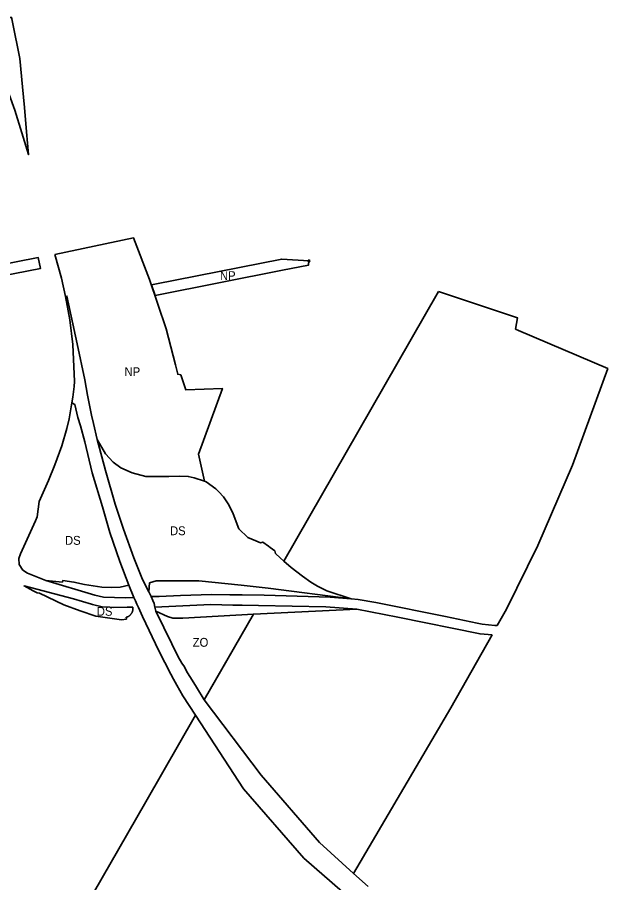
# Model space of a CAD drawing. Extents: x -650276 to -642489, y -1074311 to -1066658.
# Drawn here: x -647860 to -647061, y -1068126 to -1066956 of the extents above; entities that cross this region are included whole.
import ezdxf

# ---------------------------------------------------------------- set-up
doc = ezdxf.new("R2010")
doc.units = 0
doc.header["$LTSCALE"] = 4.8
doc.header["$PDMODE"] = 32
doc.header["$PDSIZE"] = 2.4
for name, color, linetype, lineweight in [('24', 7, 'Continuous', 35), ('25', 7, 'Continuous', 35), ('42', 7, 'Continuous', 35), ('48', 7, 'Continuous', 35)]:
    doc.layers.add(name, color=color, linetype=linetype, lineweight=lineweight)
doc.layers.add('62', color=7, linetype='Continuous')

msp = doc.modelspace()

# ---------------------------------------------------------------- linework, layer by layer
at = {"layer": '24'}
for points in [[(-647876.57, -1067043.5), (-647863.04, -1067081.36), (-647853.65, -1067111.91), (-647844.3, -1067141.25), (-647847.09, -1067110.58), (-647850.07, -1067077.71), (-647852.63, -1067049.52), (-647856.11, -1067011.21), (-647866.14, -1066961.98), (-647867.46, -1066955.52), (-647905.28, -1066967.07), (-647903.5, -1066972.05)], [(-647754.88, -1067737.59), (-647743.12, -1067739.93), (-647728.29, -1067740.64), (-647713.15, -1067741), (-647702.21, -1067740.43), (-647708.71, -1067723.99), (-647720.45, -1067726.49), (-647732.71, -1067727.02), (-647745.41, -1067726.6), (-647768.53, -1067722.82), (-647783.13, -1067719.68), (-647798.17, -1067717.58), (-647798.5, -1067719.67), (-647821.02, -1067717.33)], [(-647596.91, -1067736.61), (-647572.33, -1067737.03), (-647555.58, -1067736.71), (-647525.685, -1067737.542), (-647436.72, -1067740.02), (-647408.2, -1067742.37), (-647520.145, -1067727.879), (-647557, -1067724), (-647614, -1067718), (-647643, -1067718), (-647672, -1067718), (-647680.804, -1067720.745), (-647681.91, -1067732.74), (-647678.66, -1067739.38), (-647678.66, -1067739.38), (-647667.76, -1067739.01), (-647638.75, -1067738.03)], [(-647540.208, -1067762.876), (-647400.63, -1067756.19), (-647442.6, -1067753.13), (-647533.597, -1067751.344), (-647555.67, -1067750.91), (-647568.36, -1067750.7), (-647597.83, -1067750.21), (-647673.47, -1067753.48), (-647672.05, -1067758.98), (-647672.05, -1067758.98), (-647656.469, -1067766.309), (-647649.22, -1067768.38), (-647635.758, -1067768.38)], [(-647540.208, -1067762.876), (-647400.63, -1067756.19), (-647442.6, -1067753.13), (-647533.597, -1067751.344), (-647555.67, -1067750.91), (-647568.36, -1067750.7), (-647597.83, -1067750.21), (-647673.47, -1067753.48), (-647672.05, -1067758.98), (-647672.05, -1067758.98), (-647656.469, -1067766.309), (-647649.22, -1067768.38), (-647635.758, -1067768.38)]]:
    msp.add_lwpolyline(points, close=True, dxfattribs=at)
for points in [[(-647606.818, -1067879.061), (-647617.25, -1067861.95), (-647625.37, -1067848.86), (-647630.3, -1067841.02), (-647633.69, -1067834.31), (-647637.21, -1067829.29), (-647642.29, -1067820.76), (-647650.8, -1067803.28), (-647672.05, -1067758.98), (-647673.47, -1067753.48), (-647673.47, -1067753.48), (-647674.67, -1067748.73), (-647676.47, -1067744.5), (-647678.66, -1067739.38), (-647681.91, -1067732.74), (-647690.09, -1067716.05), (-647702.04, -1067686.86), (-647715.92, -1067648.12), (-647727.37, -1067614.33), (-647740.49, -1067568.67), (-647751.41, -1067526.58), (-647756.55, -1067505.32), (-647759.16, -1067494.01), (-647764.89, -1067466.64), (-647768.5, -1067446.04), (-647778.78, -1067397.1), (-647792.52, -1067332.74), (-647794.54, -1067333.14), (-647788.77, -1067365.03), (-647784.55, -1067398.01), (-647782.39, -1067448.34), (-647782.5, -1067455.11), (-647784.36, -1067469.6), (-647785.64, -1067477.02), (-647781.85, -1067479.19), (-647777.55, -1067496.95), (-647773.96, -1067508.48), (-647768.5, -1067529.75), (-647758.25, -1067571.79), (-647744.61, -1067617.96), (-647734.63, -1067652.57), (-647721.05, -1067691.73), (-647708.71, -1067723.99), (-647702.21, -1067740.43), (-647699.89, -1067745.24), (-647697.85, -1067749.46), (-647695.71, -1067753.9), (-647690.19, -1067766.37), (-647668.13, -1067812.76), (-647651.94, -1067844.36), (-647648.33, -1067851.17), (-647643.83, -1067859.13), (-647635.77, -1067873.43), (-647618.773, -1067899.914)], [(-647708.71, -1067723.99), (-647721.05, -1067691.73), (-647734.63, -1067652.57), (-647744.61, -1067617.96), (-647758.25, -1067571.79), (-647768.5, -1067529.75), (-647773.96, -1067508.48), (-647777.55, -1067496.95), (-647781.85, -1067479.19), (-647785.64, -1067477.02), (-647789.39, -1067498.84), (-647792.54, -1067511.85), (-647799.39, -1067535.48)], [(-647654.743, -1067576.996), (-647685.968, -1067576.68), (-647704.458, -1067572.034), (-647719.661, -1067564.884), (-647729.802, -1067557.462), (-647740.124, -1067546.265), (-647751.41, -1067526.58)], [(-647751.41, -1067526.58), (-647740.49, -1067568.67), (-647727.37, -1067614.33), (-647715.92, -1067648.12), (-647702.04, -1067686.86)], [(-647799.39, -1067535.48), (-647808.71, -1067561.03), (-647817.59, -1067582.4)], [(-647817.59, -1067582.4), (-647829.97, -1067610.62), (-647832.8, -1067631.53), (-647835.06, -1067637.01), (-647855.24, -1067681.26), (-647857.51, -1067687.74), (-647856.9, -1067695.97)], [(-647606.559, -1067583.309), (-647620.586, -1067578.478), (-647628.441, -1067576.759), (-647640.087, -1067576.306), (-647654.743, -1067576.996)], [(-647547.663, -1067659.519), (-647560.187, -1067647.458), (-647567.744, -1067627.24), (-647573.605, -1067614.951), (-647580.539, -1067604.432), (-647586.864, -1067597.411), (-647591.227, -1067593.613), (-647604.415, -1067584.047), (-647606.559, -1067583.309)], [(-647499.095, -1067691.163), (-647503.97, -1067686.73), (-647510.6, -1067680.86), (-647511.24, -1067677.53), (-647517.74, -1067672.85), (-647520.13, -1067671.13), (-647527.76, -1067665.65), (-647530.82, -1067666.65), (-647536.83, -1067663.64), (-647547.663, -1067659.519)], [(-647702.04, -1067686.86), (-647690.09, -1067716.05), (-647681.91, -1067732.74)], [(-647856.9, -1067695.97), (-647852.3, -1067703.36), (-647845.74, -1067707.59), (-647821.02, -1067717.33)], [(-647462.45, -1067719.84), (-647474.13, -1067711.81), (-647489.3, -1067700.07), (-647499.095, -1067691.163)], [(-647783.54, -1067742.11), (-647850.45, -1067724.77), (-647838.18, -1067731.62), (-647832.56, -1067734.22), (-647829.49, -1067734.58), (-647796.87, -1067750.25), (-647774.54, -1067758.68), (-647753.53, -1067765.58), (-647718.54, -1067770.6), (-647712.01, -1067769.63), (-647712.26, -1067767.28)], [(-647821.02, -1067717.33), (-647798.5, -1067719.67), (-647798.17, -1067717.58), (-647783.13, -1067719.68), (-647768.53, -1067722.82), (-647745.41, -1067726.6), (-647732.71, -1067727.02), (-647720.45, -1067726.49), (-647708.71, -1067723.99)], [(-647681.91, -1067732.74), (-647680.804, -1067720.745), (-647672, -1067718), (-647643, -1067718), (-647614, -1067718)], [(-647614, -1067718), (-647557, -1067724), (-647520.145, -1067727.879), (-647408.2, -1067742.37), (-647440.81, -1067731.38), (-647453.87, -1067724.97), (-647462.45, -1067719.84)], [(-647712.26, -1067767.28), (-647711.773, -1067767.135), (-647711.286, -1067766.968), (-647710.799, -1067766.777), (-647710.315, -1067766.562), (-647709.834, -1067766.324), (-647709.359, -1067766.062), (-647708.892, -1067765.776), (-647708.433, -1067765.466), (-647707.985, -1067765.133), (-647707.55, -1067764.777), (-647707.128, -1067764.398), (-647706.723, -1067763.999), (-647706.335, -1067763.579), (-647705.966, -1067763.14), (-647705.617, -1067762.683), (-647705.29, -1067762.21), (-647704.985, -1067761.721), (-647704.704, -1067761.22), (-647704.447, -1067760.707), (-647704.216, -1067760.184), (-647704.01, -1067759.653), (-647703.83, -1067759.117), (-647703.675, -1067758.576), (-647703.547, -1067758.033), (-647703.445, -1067757.489), (-647703.368, -1067756.946), (-647703.315, -1067756.406), (-647703.287, -1067755.87), (-647703.282, -1067755.341), (-647703.3, -1067754.818), (-647703.34, -1067754.304), (-647703.4, -1067753.8), (-647711.09, -1067753.71), (-647728.98, -1067754.07), (-647734.69, -1067753.66), (-647744.74, -1067752.93), (-647757.74, -1067749.96), (-647759.13, -1067749.54), (-647783.54, -1067742.11)], [(-647405.026, -1068113.904), (-647451.024, -1068071.886), (-647530.038, -1067980.839), (-647606.818, -1067879.061)], [(-647618.773, -1067899.914), (-647553.628, -1067999.427), (-647472.338, -1068093.096), (-647419.713, -1068138.871)], [(-647385.13, -1068131.51), (-647405.026, -1068113.904)]]:
    msp.add_lwpolyline(points, dxfattribs=at)
at = {"layer": '25'}
for points in [[(-647289.924, -1067326.309), (-647364.024, -1067455.561), (-647499.095, -1067691.163), (-647489.3, -1067700.07)], [(-647185.93, -1067377.38), (-647183.09, -1067362.16), (-647289.924, -1067326.309)], [(-647210.537, -1067778.594), (-647198.088, -1067756.5), (-647155.592, -1067670.17), (-647108.971, -1067561.55), (-647061.252, -1067430.908), (-647181.878, -1067379.12), (-647185.93, -1067377.38)], [(-647489.3, -1067700.07), (-647474.13, -1067711.81), (-647462.45, -1067719.84), (-647453.87, -1067724.97), (-647440.81, -1067731.38), (-647408.2, -1067742.37), (-647398.74, -1067743.15)], [(-647398.74, -1067743.15), (-647374.55, -1067747.34), (-647280.78, -1067766.44), (-647237.91, -1067775.18), (-647231.17, -1067776.55), (-647213.92, -1067778.26), (-647210.537, -1067778.594)], [(-647400.63, -1067756.19), (-647540.208, -1067762.876), (-647593.267, -1067855.425), (-647606.818, -1067879.061)], [(-647217.611, -1067791.149), (-647233.83, -1067789.69), (-647345.11, -1067767.28), (-647400.63, -1067756.19)], [(-647405.026, -1068113.904), (-647273.297, -1067889.981), (-647217.611, -1067791.149)], [(-647606.818, -1067879.061), (-647530.038, -1067980.839), (-647451.024, -1068071.886), (-647405.026, -1068113.904)], [(-647464.94, -1068215.752), (-647461.188, -1068209.373), (-647419.713, -1068138.871), (-647472.338, -1068093.096), (-647553.628, -1067999.427), (-647618.773, -1067899.914), (-647685.819, -1068016.861)], [(-647685.819, -1068016.861), (-647781.346, -1068183.485), (-647791.055, -1068200.507)]]:
    msp.add_lwpolyline(points, dxfattribs=at)
at = {"layer": '42'}
msp.add_lwpolyline([(-647606.818, -1067879.061), (-647540.208, -1067762.876), (-647635.758, -1067768.38), (-647649.22, -1067768.38), (-647656.469, -1067766.309), (-647672.05, -1067758.98), (-647650.8, -1067803.28), (-647642.29, -1067820.76), (-647637.21, -1067829.29), (-647633.69, -1067834.31), (-647630.3, -1067841.02), (-647625.37, -1067848.86), (-647617.25, -1067861.95)], close=True, dxfattribs=at)
at = {"layer": '48'}
for points in [[(-647638.68, -1067439.06), (-647642.686, -1067438.46), (-647645.78, -1067425.81), (-647658.13, -1067376.99), (-647680.64, -1067310.37), (-647702.42, -1067253.98), (-647809.02, -1067276.271)], [(-647882.66, -1067529.231), (-647926.759, -1067358.379), (-647937.355, -1067316.774), (-647828.376, -1067295.406), (-647828.104, -1067295.352), (-647831.28, -1067280.69), (-647948.488, -1067303.671)], [(-647809.02, -1067276.271), (-647799.76, -1067308.3), (-647794.54, -1067333.14)], [(-647465.203, -1067285.115), (-647501.968, -1067282.642), (-647673.685, -1067316.666), (-647678.21, -1067317.562), (-647673.367, -1067331.895), (-647670.77, -1067331.38), (-647501.099, -1067297.762)], [(-647501.099, -1067297.762), (-647465.699, -1067290.747), (-647465.203, -1067285.115)], [(-647794.54, -1067333.14), (-647792.52, -1067332.74), (-647778.78, -1067397.1), (-647768.5, -1067446.04), (-647764.89, -1067466.64), (-647759.16, -1067494.01)], [(-647751.41, -1067526.58), (-647740.124, -1067546.265), (-647729.802, -1067557.462), (-647719.661, -1067564.884), (-647704.458, -1067572.034), (-647685.968, -1067576.68), (-647654.743, -1067576.996), (-647640.087, -1067576.306), (-647628.441, -1067576.759), (-647620.586, -1067578.478), (-647606.559, -1067583.309), (-647614.75, -1067546.53), (-647582.2, -1067457.65), (-647631.59, -1067459.72), (-647638.68, -1067439.06)], [(-647759.16, -1067494.01), (-647756.55, -1067505.32), (-647751.41, -1067526.58)]]:
    msp.add_lwpolyline(points, dxfattribs=at)
msp.add_point((-647465.203, -1067285.115), dxfattribs=at)

# ---------------------------------------------------------------- texts
at = {"layer": '62', "width": 0.95}
for s, p in [('NP', (-647585.583, -1067311.041)), ('NP', (-647714.583, -1067441.041)), ('DS', (-647653.118, -1067656.225)), ('DS', (-647795.118, -1067669.225)), ('DS', (-647752.118, -1067765.225)), ('ZO', (-647622.423, -1067807.188))]:
    msp.add_text(s, height=12, dxfattribs=at).set_placement(p)

doc.saveas('drawing.dxf')
